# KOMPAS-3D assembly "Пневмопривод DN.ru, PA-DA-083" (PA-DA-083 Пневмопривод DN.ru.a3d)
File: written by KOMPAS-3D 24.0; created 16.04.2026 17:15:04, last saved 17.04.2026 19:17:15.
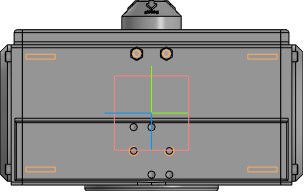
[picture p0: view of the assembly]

Document properties: Автор: DN.ru; Полное имя файла: C:\Работа\PA-DA-х Пневмопривод DN.ru\083\исходные материалы\PA-DA-083 Пневмопривод DN.ru.a3d

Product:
- Component [detail]: Пневмопривод DN.ru  | designation PA-DA-083  | qty 1  | pos. 1  | Масса: 3.1; Раздел спецификации: Прочие изделия; Примечание: D290-00295; Автор: DN.ru; source file: PA-DA-083 Пневмопривод DN.ru.m3d
- Component [standard]: Винт М4-6gx30 ГОСТ 11738-84  | qty 8  | Масса: 0.00361; Раздел спецификации: Стандартные изделия; Рассекать на разрезах: no
- Component [standard]: Болт М5-6gx50 ГОСТ 7805-70  | qty 2  | Масса: 0.008999; Раздел спецификации: Стандартные изделия; Рассекать на разрезах: no
- Component [standard]: Гайка М5-6H ГОСТ 5915-70  | qty 2  | Масса: 0.00144; Раздел спецификации: Стандартные изделия; Рассекать на разрезах: no
- Part/product: Пневмопривод DN.ru  | designation PA-DA-083
    Масса: 3.1
    Раздел спецификации: Прочие изделия
    Примечание: D290-00295

Expressions: D290-00293; D290-00295
Referenced files in C:\Работа\PA-DA-х Пневмопривод DN.ru\052\исходные материалы\: PA-DA-052 Пневмопривод DN.ru.m3d
Referenced files in C:\Работа\PA-DA-х Пневмопривод DN.ru\083\исходные материалы\: PA-DA-083 Пневмопривод DN.ru.m3d
Referenced files in C:\Program Files\ASCON\KOMPAS-3D v24\Libs\PolynomLib\DATA\vault\Methods\Kompas\3D\: PLib_Screw_GOST_11738_1500.m3d, PLib_Bolt_1_900.m3d, PLib_Nut_OST92_900.m3d
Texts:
  PA-DA-052
  Крепежное изделие ГОСТ
  BOSimple***PART:1ff84fa3-e62c-5a6d-126f-35e3f1af4542***SHORTLOC:Root±30±20±10±80±10±GMC90[Нет;Без покрытия;Без указания материала;0,7;-;30;4]
  BOSimple***PART:53acba15-081d-1c02-6810-072b309dd366***SHORTLOC:Root±30±20±10±80±10±©{}30±©{BASE}130±30[Нет;Без покрытия;Без указания материала;50;5;8;0,8;-]
  BOSimple***PART:0338bb82-6b79-df62-da33-8b23172f1b3e***SHORTLOC:Root±30±10±20±©{}110±10±50±60[Нет;Без покрытия;Без указания материала;-;5;0,8;8]
  Программные изделия  и базы данных
  PA-DA-083
  PA-DA-083 Пневмопривод DN.ru
  Винт М4-6gx30 ГОСТ 11738-84 (1)
  Винт М4-6gx30 ГОСТ 11738-84 (2)
  Винт М4-6gx30 ГОСТ 11738-84 (3)
  Винт М4-6gx30 ГОСТ 11738-84 (4)
  Винт М4-6gx30 ГОСТ 11738-84 (5)
  Винт М4-6gx30 ГОСТ 11738-84 (6)
  Винт М4-6gx30 ГОСТ 11738-84 (7)
  Винт М4-6gx30 ГОСТ 11738-84 (8)
  Болт М5-6gx50 ГОСТ 7805-70 (1)
  hole1
  hole2
  Болт М5-6gx50 ГОСТ 7805-70 (2)
  Гайка М5-6H ГОСТ 5915-70 (1)
  bcut1
  hcut1
  cut1
  Гайка М5-6H ГОСТ 5915-70 (2)
  Plane. Начало координат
